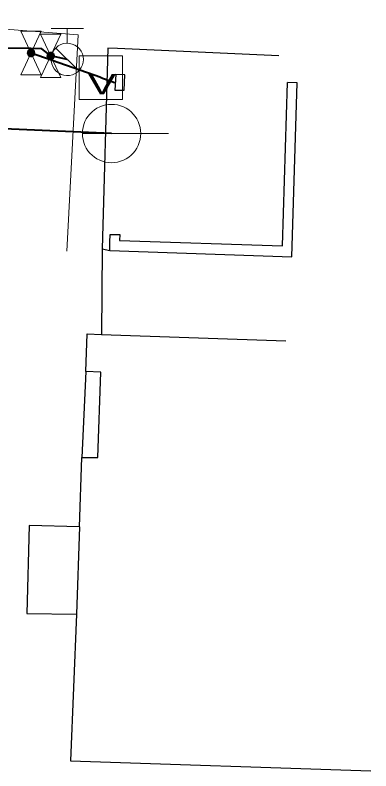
# Model space of a CAD drawing. Extents: x -968691 to -140888, y -1376050 to -879856.
# Drawn here: x -646109.94 to -646097.65, y -1062448.38 to -1062422.27 of the extents above; entities that cross this region are included whole.
import ezdxf
from ezdxf.enums import TextEntityAlignment as Align

# ---------------------------------------------------------------- set-up
doc = ezdxf.new("R2010")
doc.units = 0
doc.header["$LTSCALE"] = 4.8
for name, pattern in [('DOT_DASHED', [7.7, 5, -1.2, 0.3, -1.2]), ('DOTTED', [1.5, 0.3, -1.2]), ('LONG_DASHED', [7.5, 6, -1.5]), ('MEDIUM_DASHED', [4.5, 3, -1.5])]:
    doc.linetypes.add(name, pattern=pattern)
doc.layers.add('1', color=7, linetype='Continuous', lineweight=13)

msp = doc.modelspace()

# ---------------------------------------------------------------- hatches: boundary and pattern name
at = {"layer": '1'}
for points in [[(-646109.258, -1062423.58), (-646109.26, -1062423.556), (-646109.267, -1062423.533), (-646109.277, -1062423.511), (-646109.291, -1062423.492), (-646109.309, -1062423.475), (-646109.329, -1062423.462), (-646109.352, -1062423.453), (-646109.375, -1062423.449), (-646109.399, -1062423.448), (-646109.423, -1062423.452), (-646109.446, -1062423.46), (-646109.467, -1062423.472), (-646109.485, -1062423.488), (-646109.5, -1062423.507), (-646109.512, -1062423.528), (-646109.519, -1062423.551), (-646109.522, -1062423.575), (-646109.521, -1062423.599), (-646109.515, -1062423.622), (-646109.505, -1062423.644), (-646109.492, -1062423.664), (-646109.475, -1062423.681), (-646109.455, -1062423.695), (-646109.433, -1062423.705), (-646109.41, -1062423.711), (-646109.386, -1062423.712), (-646109.362, -1062423.709), (-646109.339, -1062423.702), (-646109.318, -1062423.691), (-646109.299, -1062423.676), (-646109.283, -1062423.657), (-646109.271, -1062423.637), (-646109.262, -1062423.614), (-646109.258, -1062423.59)], [(-646108.578, -1062423.68), (-646108.58, -1062423.656), (-646108.587, -1062423.633), (-646108.597, -1062423.611), (-646108.611, -1062423.592), (-646108.629, -1062423.575), (-646108.649, -1062423.562), (-646108.672, -1062423.553), (-646108.695, -1062423.549), (-646108.719, -1062423.548), (-646108.743, -1062423.552), (-646108.766, -1062423.56), (-646108.787, -1062423.572), (-646108.805, -1062423.588), (-646108.82, -1062423.607), (-646108.832, -1062423.628), (-646108.839, -1062423.651), (-646108.842, -1062423.675), (-646108.841, -1062423.699), (-646108.835, -1062423.722), (-646108.825, -1062423.744), (-646108.812, -1062423.764), (-646108.795, -1062423.781), (-646108.775, -1062423.795), (-646108.753, -1062423.805), (-646108.73, -1062423.811), (-646108.706, -1062423.812), (-646108.682, -1062423.809), (-646108.659, -1062423.802), (-646108.638, -1062423.791), (-646108.619, -1062423.776), (-646108.603, -1062423.757), (-646108.591, -1062423.737), (-646108.582, -1062423.714), (-646108.578, -1062423.69)]]:
    msp.add_hatch(color=256, dxfattribs=at).paths.add_polyline_path(points)

# ---------------------------------------------------------------- linework, layer by layer
for p, q in [((-646108.699, -1062422.73), (-646107.581, -1062422.73)), ((-646108.14, -1062423.242), (-646108.14, -1062422.73)), ((-646107.76, -1062422.95), (-646108.156, -1062430.418)), ((-646109.4, -1062423.42), (-646109.39, -1062423.58)), ((-646106.98, -1062424.43), (-646109.39, -1062423.58)), ((-646107.745, -1062424.196), (-646108.535, -1062423.406)), ((-646106.98, -1062424.43), (-646106.508, -1062424.596)), ((-646106.61, -1062426.36), (-646115.201, -1062425.99)), ((-646107.618, -1062426.36), (-646104.642, -1062426.36))]:
    msp.add_line(p, q, dxfattribs=at)
at = {"layer": '1', "linetype": 'LONG_DASHED', "lineweight": 40}
for p, q in [((-646109.4, -1062423.42), (-646109.39, -1062423.58)), ((-646106.98, -1062424.43), (-646109.39, -1062423.58)), ((-646106.61, -1062426.36), (-646115.201, -1062425.99))]:
    msp.add_line(p, q, dxfattribs=at)
at = {"layer": '1', "linetype": 'MEDIUM_DASHED', "lineweight": 25}
for p, q in [((-646106.74, -1062423.409), (-646106.932, -1062430.348)), ((-646106.932, -1062430.348), (-646106.959, -1062433.297)), ((-646106.932, -1062430.348), (-646106.675, -1062430.398)), ((-646107.503, -1062434.583), (-646107.633, -1062437.548))]:
    msp.add_line(p, q, dxfattribs=at)
at = {"layer": '1', "lineweight": 25}
for p, q in [((-646106.459, -1062424.323), (-646106.497, -1062424.859)), ((-646100.204, -1062424.614), (-646100.534, -1062424.599)), ((-646100.387, -1062430.625), (-646100.204, -1062424.614)), ((-646106.675, -1062430.398), (-646100.387, -1062430.625)), ((-646107.503, -1062434.583), (-646107.455, -1062433.279)), ((-646107.455, -1062433.279), (-646106.959, -1062433.297)), ((-646106.959, -1062433.297), (-646100.594, -1062433.523)), ((-646107.722, -1062439.945), (-646107.633, -1062437.548))]:
    msp.add_line(p, q, dxfattribs=at)
at = {"layer": '1', "linetype": 'DOT_DASHED', "lineweight": 25}
for p, q in [((-646106.152, -1062424.337), (-646106.459, -1062424.323)), ((-646100.705, -1062430.236), (-646100.534, -1062424.599)), ((-646106.667, -1062430.114), (-646106.659, -1062429.846)), ((-646106.659, -1062429.846), (-646106.326, -1062429.846)), ((-646106.326, -1062429.846), (-646106.332, -1062430.057)), ((-646106.675, -1062430.398), (-646106.667, -1062430.114)), ((-646106.332, -1062430.057), (-646100.705, -1062430.236)), ((-646106.975, -1062434.607), (-646107.503, -1062434.583)), ((-646107.722, -1062439.945), (-646107.819, -1062442.967))]:
    msp.add_line(p, q, dxfattribs=at)
at = {"layer": '1', "linetype": 'DOTTED', "lineweight": 40}
msp.add_line((-646106.98, -1062424.43), (-646106.508, -1062424.596), dxfattribs=at)
at = {"layer": '1'}
msp.add_lwpolyline([(-646117.41, -1062422.27), (-646110.271, -1062422.754), (-646107.76, -1062422.95)], dxfattribs=at)
for points in [[(-646109.74, -1062422.83), (-646109.04, -1062422.83), (-646109.74, -1062424.33), (-646109.04, -1062424.33)], [(-646109.06, -1062422.93), (-646108.36, -1062422.93), (-646109.06, -1062424.43), (-646108.36, -1062424.43)], [(-646107.581, -1062423.8), (-646107.59, -1062423.701), (-646107.617, -1062423.604), (-646107.661, -1062423.514), (-646107.72, -1062423.432), (-646107.792, -1062423.363), (-646107.876, -1062423.308), (-646107.968, -1062423.269), (-646108.066, -1062423.247), (-646108.166, -1062423.242), (-646108.266, -1062423.256), (-646108.361, -1062423.287), (-646108.449, -1062423.335), (-646108.528, -1062423.398), (-646108.593, -1062423.474), (-646108.644, -1062423.56), (-646108.679, -1062423.654), (-646108.697, -1062423.753), (-646108.696, -1062423.853), (-646108.678, -1062423.952), (-646108.642, -1062424.046), (-646108.59, -1062424.131), (-646108.524, -1062424.207), (-646108.445, -1062424.269), (-646108.356, -1062424.316), (-646108.261, -1062424.346), (-646108.161, -1062424.359), (-646108.061, -1062424.354), (-646107.963, -1062424.331), (-646107.871, -1062424.29), (-646107.788, -1062424.235), (-646107.716, -1062424.165), (-646107.658, -1062424.083), (-646107.615, -1062423.992), (-646107.589, -1062423.895)], [(-646109.258, -1062423.58), (-646109.26, -1062423.556), (-646109.267, -1062423.533), (-646109.277, -1062423.511), (-646109.291, -1062423.492), (-646109.309, -1062423.475), (-646109.329, -1062423.462), (-646109.352, -1062423.453), (-646109.375, -1062423.449), (-646109.399, -1062423.448), (-646109.423, -1062423.452), (-646109.446, -1062423.46), (-646109.467, -1062423.472), (-646109.485, -1062423.488), (-646109.5, -1062423.507), (-646109.512, -1062423.528), (-646109.519, -1062423.551), (-646109.522, -1062423.575), (-646109.521, -1062423.599), (-646109.515, -1062423.622), (-646109.505, -1062423.644), (-646109.492, -1062423.664), (-646109.475, -1062423.681), (-646109.455, -1062423.695), (-646109.433, -1062423.705), (-646109.41, -1062423.711), (-646109.386, -1062423.712), (-646109.362, -1062423.709), (-646109.339, -1062423.702), (-646109.318, -1062423.691), (-646109.299, -1062423.676), (-646109.283, -1062423.657), (-646109.271, -1062423.637), (-646109.262, -1062423.614), (-646109.258, -1062423.59)], [(-646108.578, -1062423.68), (-646108.58, -1062423.656), (-646108.587, -1062423.633), (-646108.597, -1062423.611), (-646108.611, -1062423.592), (-646108.629, -1062423.575), (-646108.649, -1062423.562), (-646108.672, -1062423.553), (-646108.695, -1062423.549), (-646108.719, -1062423.548), (-646108.743, -1062423.552), (-646108.766, -1062423.56), (-646108.787, -1062423.572), (-646108.805, -1062423.588), (-646108.82, -1062423.607), (-646108.832, -1062423.628), (-646108.839, -1062423.651), (-646108.842, -1062423.675), (-646108.841, -1062423.699), (-646108.835, -1062423.722), (-646108.825, -1062423.744), (-646108.812, -1062423.764), (-646108.795, -1062423.781), (-646108.775, -1062423.795), (-646108.753, -1062423.805), (-646108.73, -1062423.811), (-646108.706, -1062423.812), (-646108.682, -1062423.809), (-646108.659, -1062423.802), (-646108.638, -1062423.791), (-646108.619, -1062423.776), (-646108.603, -1062423.757), (-646108.591, -1062423.737), (-646108.582, -1062423.714), (-646108.578, -1062423.69)], [(-646107.73, -1062425.18), (-646106.23, -1062425.18), (-646106.23, -1062423.68), (-646107.73, -1062423.68)], [(-646106.61, -1062425.352), (-646106.715, -1062425.358), (-646106.819, -1062425.374), (-646106.921, -1062425.402), (-646107.02, -1062425.44), (-646107.114, -1062425.487), (-646107.202, -1062425.545), (-646107.284, -1062425.611), (-646107.359, -1062425.686), (-646107.425, -1062425.768), (-646107.483, -1062425.856), (-646107.53, -1062425.95), (-646107.568, -1062426.049), (-646107.596, -1062426.151), (-646107.612, -1062426.255), (-646107.618, -1062426.36), (-646107.612, -1062426.465), (-646107.596, -1062426.57), (-646107.568, -1062426.672), (-646107.53, -1062426.77), (-646107.483, -1062426.864), (-646107.425, -1062426.953), (-646107.359, -1062427.035), (-646107.284, -1062427.109), (-646107.202, -1062427.175), (-646107.114, -1062427.233), (-646107.02, -1062427.281), (-646106.921, -1062427.319), (-646106.819, -1062427.346), (-646106.715, -1062427.362), (-646106.61, -1062427.368), (-646106.505, -1062427.362), (-646106.4, -1062427.346), (-646106.298, -1062427.319), (-646106.2, -1062427.281), (-646106.106, -1062427.233), (-646106.017, -1062427.175), (-646105.935, -1062427.109), (-646105.861, -1062427.035), (-646105.795, -1062426.953), (-646105.737, -1062426.864), (-646105.689, -1062426.77), (-646105.651, -1062426.672), (-646105.624, -1062426.57), (-646105.608, -1062426.465), (-646105.602, -1062426.36), (-646105.608, -1062426.255), (-646105.624, -1062426.151), (-646105.651, -1062426.049), (-646105.689, -1062425.95), (-646105.737, -1062425.856), (-646105.795, -1062425.768), (-646105.861, -1062425.686), (-646105.935, -1062425.611), (-646106.017, -1062425.545), (-646106.106, -1062425.487), (-646106.2, -1062425.44), (-646106.298, -1062425.402), (-646106.4, -1062425.374), (-646106.505, -1062425.358)]]:
    msp.add_lwpolyline(points, close=True, dxfattribs=at)
at = {"layer": '1', "linetype": 'LONG_DASHED', "lineweight": 40}
msp.add_lwpolyline([(-646108.14, -1062423.8), (-646108.71, -1062423.68), (-646109.02, -1062423.43), (-646109.4, -1062423.42), (-646112.39, -1062423.39), (-646114.9, -1062423.11), (-646115.47, -1062433.81)], dxfattribs=at)
at = {"layer": '1', "lineweight": 35}
msp.add_lwpolyline([(-646108.14, -1062423.8), (-646108.71, -1062423.68), (-646109.02, -1062423.43), (-646109.4, -1062423.42), (-646112.39, -1062423.39), (-646114.9, -1062423.11), (-646115.47, -1062433.81)], dxfattribs=at)
at = {"layer": '1', "linetype": 'MEDIUM_DASHED', "lineweight": 25}
for points in [[(-646100.836, -1062423.677), (-646106.403, -1062423.424), (-646106.74, -1062423.409)], [(-646107.722, -1062439.945), (-646109.46, -1062439.905), (-646109.533, -1062442.935), (-646107.819, -1062442.967)]]:
    msp.add_lwpolyline(points, dxfattribs=at)
at = {"layer": '1', "linetype": 'DOT_DASHED', "lineweight": 25}
for points in [[(-646106.497, -1062424.859), (-646106.18, -1062424.859), (-646106.152, -1062424.337)], [(-646107.633, -1062437.548), (-646107.081, -1062437.548), (-646106.975, -1062434.607)]]:
    msp.add_lwpolyline(points, dxfattribs=at)
at = {"layer": '1', "lineweight": 25}
msp.add_lwpolyline([(-646107.819, -1062442.967), (-646108.031, -1062448.026), (-646097.654, -1062448.376)], dxfattribs=at)

# ---------------------------------------------------------------- texts
at = {"layer": '1', "width": 1.55}
msp.add_text('V', height=0.7, dxfattribs=at).set_placement((-646106.941, -1062425.009), align=Align.CENTER)

doc.saveas('drawing.dxf')
